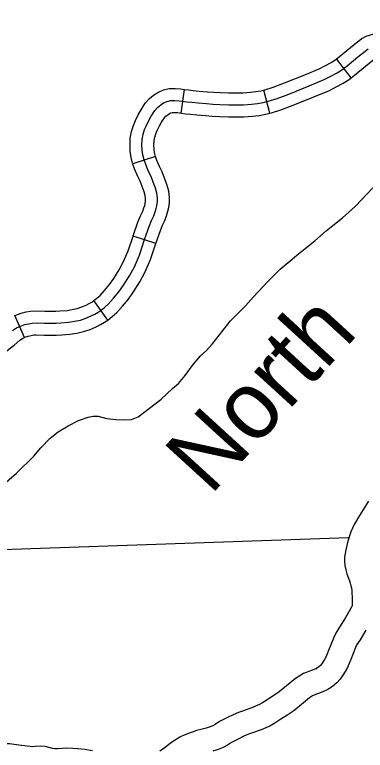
# Model space of a CAD drawing. Extents: x -3711 to 825, y -151 to 1050.
# Drawn here: x -2822.7 to -2798.1, y 424.3 to 475.9 of the extents above; entities that cross this region are included whole.
import ezdxf

# ---------------------------------------------------------------- set-up
doc = ezdxf.new("R2010")
doc.units = 0
for name, color, linetype in [('Level 32', 7, 'Continuous'), ('Level 35', 7, 'Continuous'), ('Level 46', 7, 'Continuous'), ('Level 5', 7, 'Continuous')]:
    doc.layers.add(name, color=color, linetype=linetype)

msp = doc.modelspace()

# ---------------------------------------------------------------- linework, layer by layer
at = {"layer": 'Level 32'}
for p, q in [((-2799.107, 471.492), (-2800.149, 472.812)), ((-2811.041, 469.005), (-2810.815, 470.671)), ((-2804.825, 468.996), (-2805.253, 470.621)), ((-2812.846, 465.962), (-2814.441, 465.431)), ((-2812.823, 459.842), (-2814.419, 460.369)), ((-2816.207, 454.469), (-2817.176, 455.842)), ((-2822.049, 453.249), (-2822.738, 454.783))]:
    msp.add_line(p, q, dxfattribs=at)
for points in [[(-2800.149, 472.812), (-2799.935, 472.981), (-2799.172, 473.614), (-2798.65, 474.03), (-2798.371, 474.236), (-2798.06, 474.399), (-2797.532, 474.579), (-2797.033, 474.749), (-2796.75, 474.819), (-2796.512, 474.91), (-2796.35, 474.988), (-2796.202, 475.079), (-2795.938, 475.307), (-2795.322, 475.913)], [(-2799.107, 471.492), (-2798.877, 471.674), (-2798.111, 472.31), (-2797.626, 472.696), (-2797.476, 472.807), (-2797.395, 472.85), (-2796.99, 472.987), (-2796.557, 473.135), (-2796.244, 473.213), (-2795.847, 473.365), (-2795.543, 473.511), (-2795.206, 473.718), (-2794.799, 474.069), (-2794.143, 474.714)], [(-2813.718, 467.522), (-2813.615, 467.849), (-2813.494, 468.129), (-2813.317, 468.493), (-2813.149, 468.8), (-2812.897, 469.183), (-2812.701, 469.407), (-2812.478, 469.584), (-2812.282, 469.724), (-2812.039, 469.827), (-2811.797, 469.883), (-2811.489, 469.892), (-2811.191, 469.873), (-2810.641, 469.799), (-2810.305, 469.762), (-2809.867, 469.715), (-2809.28, 469.668), (-2808.823, 469.631), (-2808.328, 469.603), (-2807.704, 469.584), (-2807.256, 469.594), (-2806.669, 469.594), (-2806.109, 469.631), (-2805.69, 469.678), (-2805.289, 469.743), (-2804.935, 469.836), (-2804.319, 470.032), (-2803.499, 470.34), (-2802.054, 470.918), (-2801, 471.357), (-2800.543, 471.59), (-2800.096, 471.824), (-2799.76, 472.047), (-2799.406, 472.327), (-2798.641, 472.962), (-2798.138, 473.363), (-2797.923, 473.522)], [(-2805.253, 470.621), (-2805.169, 470.644), (-2804.595, 470.827), (-2803.803, 471.124), (-2802.371, 471.697), (-2801.353, 472.121), (-2800.929, 472.337), (-2800.524, 472.548), (-2800.255, 472.728), (-2800.149, 472.812)], [(-2804.825, 468.996), (-2804.7, 469.029), (-2804.044, 469.238), (-2803.195, 469.556), (-2801.736, 470.14), (-2800.647, 470.594), (-2800.158, 470.843), (-2799.667, 471.099), (-2799.265, 471.367), (-2799.107, 471.492)], [(-2814.442, 465.431), (-2814.458, 465.479), (-2814.57, 465.897), (-2814.631, 466.323), (-2814.643, 466.766), (-2814.62, 467.242), (-2814.536, 467.721), (-2814.404, 468.142), (-2814.258, 468.48), (-2814.064, 468.878), (-2813.87, 469.233), (-2813.568, 469.693), (-2813.284, 470.018), (-2812.983, 470.256), (-2812.695, 470.462), (-2812.3, 470.629), (-2811.905, 470.721), (-2811.476, 470.734), (-2811.108, 470.711), (-2810.815, 470.671)], [(-2810.815, 470.671), (-2810.538, 470.633), (-2810.214, 470.597), (-2809.789, 470.552), (-2809.212, 470.506), (-2808.765, 470.47), (-2808.292, 470.443), (-2807.7, 470.425), (-2807.265, 470.434), (-2806.697, 470.434), (-2806.184, 470.468), (-2805.804, 470.511), (-2805.464, 470.566), (-2805.253, 470.622)], [(-2812.846, 465.962), (-2812.847, 465.964), (-2812.921, 466.236), (-2812.953, 466.464), (-2812.96, 466.748), (-2812.946, 467.056), (-2812.899, 467.323), (-2812.826, 467.555), (-2812.73, 467.777), (-2812.569, 468.107), (-2812.427, 468.368), (-2812.226, 468.673), (-2812.119, 468.796), (-2811.972, 468.912), (-2811.868, 468.986), (-2811.779, 469.024), (-2811.689, 469.045), (-2811.503, 469.051), (-2811.274, 469.036), (-2811.041, 469.005)], [(-2811.041, 469.005), (-2810.744, 468.964), (-2810.396, 468.926), (-2809.945, 468.878), (-2809.347, 468.83), (-2808.881, 468.792), (-2808.365, 468.763), (-2807.708, 468.743), (-2807.248, 468.753), (-2806.641, 468.753), (-2806.035, 468.793), (-2805.576, 468.844), (-2805.114, 468.92), (-2804.825, 468.996)], [(-2822.883, 453.732), (-2822.612, 453.918), (-2822.342, 454.04), (-2822.034, 454.152), (-2821.764, 454.217), (-2821.512, 454.263), (-2821.242, 454.282), (-2820.636, 454.263), (-2819.834, 454.245), (-2819.489, 454.273), (-2818.957, 454.319), (-2818.538, 454.385), (-2818.126, 454.476), (-2817.735, 454.606), (-2817.364, 454.766), (-2817.104, 454.897), (-2816.874, 455.027), (-2816.673, 455.169), (-2816.433, 455.358), (-2816.151, 455.607), (-2815.797, 455.999), (-2815.424, 456.456), (-2815.088, 456.913), (-2814.678, 457.585), (-2814.333, 458.22), (-2813.979, 459.022), (-2813.615, 460.123), (-2813.298, 461.047), (-2813.13, 461.467), (-2812.981, 461.793), (-2812.869, 462.073), (-2812.795, 462.316), (-2812.757, 462.502), (-2812.72, 462.792), (-2812.72, 463.025), (-2812.757, 463.379), (-2812.85, 463.725), (-2813.009, 464.145), (-2813.167, 464.555), (-2813.335, 464.9), (-2813.54, 465.385), (-2813.652, 465.721), (-2813.746, 466.067), (-2813.792, 466.393), (-2813.801, 466.757), (-2813.783, 467.149), (-2813.718, 467.522)], [(-2812.823, 459.842), (-2812.818, 459.855), (-2812.51, 460.754), (-2812.357, 461.136), (-2812.208, 461.462), (-2812.076, 461.793), (-2811.979, 462.109), (-2811.927, 462.366), (-2811.879, 462.738), (-2811.879, 463.069), (-2811.928, 463.534), (-2812.05, 463.983), (-2812.224, 464.444), (-2812.396, 464.891), (-2812.57, 465.248), (-2812.753, 465.682), (-2812.846, 465.962)], [(-2814.419, 460.369), (-2814.412, 460.391), (-2814.086, 461.339), (-2813.903, 461.797), (-2813.754, 462.124), (-2813.662, 462.353), (-2813.611, 462.522), (-2813.587, 462.639), (-2813.561, 462.846), (-2813.561, 462.981), (-2813.586, 463.225), (-2813.651, 463.466), (-2813.794, 463.845), (-2813.939, 464.219), (-2814.101, 464.553), (-2814.328, 465.089), (-2814.441, 465.43)], [(-2817.176, 455.842), (-2817.176, 455.843), (-2816.972, 456.003), (-2816.743, 456.206), (-2816.435, 456.547), (-2816.089, 456.971), (-2815.787, 457.382), (-2815.406, 458.005), (-2815.088, 458.591), (-2814.764, 459.324), (-2814.419, 460.369)], [(-2816.207, 454.469), (-2816.17, 454.495), (-2815.894, 454.712), (-2815.559, 455.008), (-2815.159, 455.451), (-2814.759, 455.941), (-2814.389, 456.445), (-2813.95, 457.165), (-2813.578, 457.848), (-2813.193, 458.72), (-2812.823, 459.842)], [(-2822.737, 454.783), (-2822.658, 454.819), (-2822.277, 454.958), (-2821.939, 455.039), (-2821.618, 455.099), (-2821.258, 455.124), (-2820.613, 455.104), (-2819.858, 455.086), (-2819.56, 455.11), (-2819.059, 455.154), (-2818.693, 455.211), (-2818.35, 455.287), (-2818.036, 455.392), (-2817.72, 455.529), (-2817.499, 455.639), (-2817.324, 455.738), (-2817.176, 455.842)], [(-2822.049, 453.249), (-2822.026, 453.26), (-2821.791, 453.345), (-2821.589, 453.394), (-2821.406, 453.428), (-2821.226, 453.441), (-2820.658, 453.423), (-2819.81, 453.403), (-2819.418, 453.435), (-2818.856, 453.485), (-2818.383, 453.558), (-2817.902, 453.664), (-2817.435, 453.82), (-2817.009, 454.004), (-2816.709, 454.155), (-2816.423, 454.316), (-2816.207, 454.469)], [(-2824.548, 449.18), (-2824.517, 449.449), (-2824.481, 449.865), (-2824.434, 450.185), (-2824.338, 450.584), (-2824.186, 451.059), (-2824.067, 451.379), (-2823.927, 451.625), (-2823.751, 451.869), (-2823.504, 452.116), (-2823.144, 452.425), (-2822.786, 452.72), (-2822.375, 453.061), (-2822.198, 453.183), (-2822.049, 453.249)]]:
    msp.add_lwpolyline(points, dxfattribs=at)
at = {"layer": 'Level 35'}
for points in [[(-2820.238, 446.182), (-2819.692, 446.623), (-2818.978, 447.043), (-2818.264, 447.421), (-2817.592, 447.652), (-2817.235, 447.715), (-2816.879, 447.715), (-2816.27, 447.568), (-2815.64, 447.484), (-2815.052, 447.463), (-2814.527, 447.484), (-2814.065, 447.673), (-2812.469, 448.892), (-2811.651, 449.669), (-2811.231, 450.027), (-2811, 450.3), (-2810.769, 450.573), (-2810.286, 451.266), (-2809.719, 451.939), (-2809.278, 452.338), (-2808.879, 452.779), (-2807.577, 454.418), (-2806.528, 455.469), (-2805.982, 456.099), (-2804.953, 457.213), (-2804.092, 458.053), (-2803.252, 458.746), (-2802.937, 459.02), (-2802.454, 459.398), (-2801.656, 460.028), (-2800.859, 460.743), (-2800.397, 461.121), (-2799.725, 461.646), (-2799.284, 462.045), (-2798.801, 462.465), (-2797.583, 463.747)], [(-2823.681, 442.778), (-2822.61, 443.723), (-2821.393, 444.921), (-2820.91, 445.509), (-2820.238, 446.182)]]:
    msp.add_lwpolyline(points, dxfattribs=at)
at = {"layer": 'Level 46'}
for p, q in [((-2801.599, 429.989), (-2801.528, 430.03)), ((-2800.682, 428.579), (-2800.753, 428.538))]:
    msp.add_line(p, q, dxfattribs=at)
for points in [[(-2797.903, 441.753), (-2798.524, 440.76), (-2798.898, 440.128), (-2799.132, 439.607), (-2799.34, 438.946), (-2799.482, 438.332), (-2799.574, 437.816), (-2799.574, 437.548), (-2799.559, 437.249), (-2799.497, 436.939), (-2799.413, 436.643), (-2799.229, 436.167), (-2799.177, 435.986), (-2799.131, 435.809), (-2799.1, 435.661), (-2799.075, 435.456), (-2799.045, 434.858), (-2799.045, 434.609), (-2799.045, 434.403), (-2799.068, 434.36), (-2799.545, 433.544), (-2799.925, 432.899), (-2800.164, 432.523), (-2800.341, 432.182), (-2800.7, 431.274), (-2800.899, 430.797), (-2800.986, 430.63), (-2801.101, 430.445), (-2801.194, 430.309), (-2801.272, 430.225), (-2801.42, 430.105), (-2801.599, 429.989)], [(-2798.095, 432.693), (-2798.492, 432.021), (-2798.706, 431.683), (-2798.81, 431.484), (-2799.142, 430.642), (-2799.375, 430.083), (-2799.525, 429.796), (-2799.691, 429.528), (-2799.879, 429.253), (-2800.124, 428.991), (-2800.43, 428.744), (-2800.682, 428.579)], [(-2801.528, 430.03), (-2801.761, 429.909), (-2801.963, 429.842), (-2802.206, 429.757), (-2802.466, 429.65), (-2802.721, 429.5), (-2803.03, 429.293), (-2803.659, 428.79), (-2804.16, 428.37), (-2804.467, 428.165), (-2804.951, 427.864), (-2805.348, 427.603), (-2805.593, 427.462), (-2805.78, 427.377), (-2806.042, 427.271), (-2806.668, 427.041), (-2807.025, 426.918), (-2807.41, 426.764), (-2807.789, 426.562), (-2808.349, 426.276), (-2808.661, 426.076), (-2808.834, 425.982), (-2809.012, 425.907), (-2809.285, 425.825), (-2809.576, 425.745), (-2809.969, 425.65), (-2810.271, 425.537), (-2810.538, 425.44), (-2810.834, 425.332), (-2811.001, 425.263), (-2811.146, 425.184), (-2811.516, 424.957), (-2811.833, 424.741), (-2812.25, 424.401), (-2812.547, 424.19)], [(-2800.753, 428.538), (-2801.103, 428.356), (-2801.419, 428.251), (-2801.608, 428.185), (-2801.715, 428.141), (-2801.827, 428.075), (-2802.036, 427.935), (-2802.594, 427.489), (-2803.151, 427.022), (-2803.556, 426.752), (-2804.044, 426.448), (-2804.467, 426.17), (-2804.826, 425.964), (-2805.114, 425.833), (-2805.435, 425.703), (-2806.105, 425.457), (-2806.439, 425.342), (-2806.701, 425.237), (-2807.013, 425.071), (-2807.51, 424.817), (-2807.803, 424.629), (-2808.105, 424.464), (-2808.445, 424.322), (-2808.82, 424.21)], [(-2817.285, 424.226), (-2817.825, 424.316), (-2818.296, 424.375), (-2818.638, 424.399), (-2819.081, 424.412), (-2819.741, 424.357), (-2819.939, 424.357), (-2820.086, 424.385), (-2820.337, 424.469), (-2820.579, 424.521), (-2820.899, 424.553), (-2821.3, 424.538), (-2821.476, 424.514), (-2822.441, 424.621), (-2823.113, 424.713), (-2823.396, 424.713)]]:
    msp.add_lwpolyline(points, dxfattribs=at)
at = {"layer": 'Level 5'}
msp.add_lwpolyline([(-2799.294, 439.186), (-2834.462, 437.954), (-2836.254, 437.928)], dxfattribs=at)

# ---------------------------------------------------------------- texts
at = {"layer": 'Level 35'}
msp.add_text('North', height=4.7343, rotation=47.5661, dxfattribs=at).set_placement((-2809.002, 442.095))

doc.saveas('drawing.dxf')
